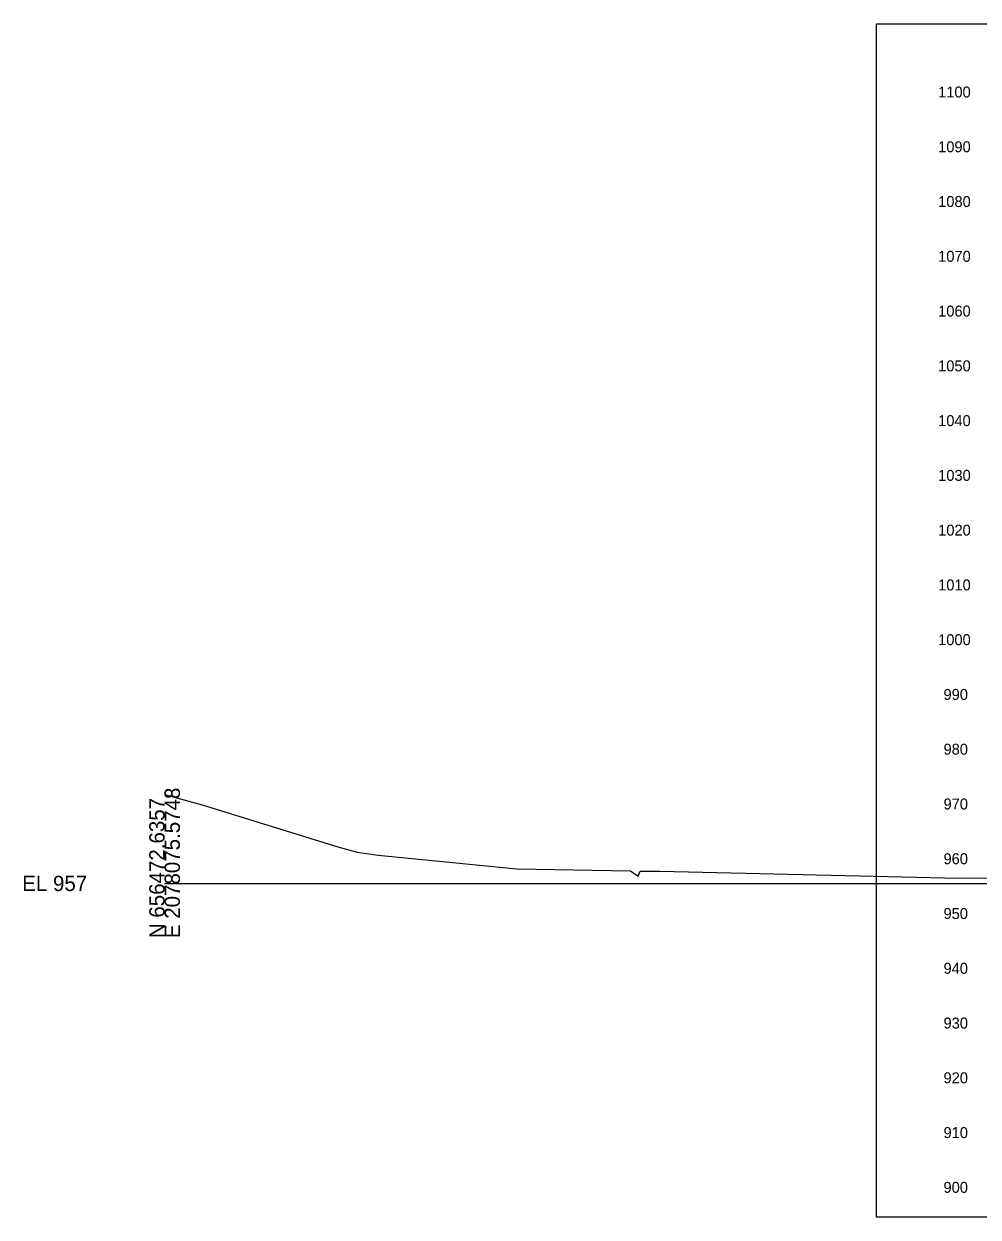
# Model space of a CAD drawing. Extents: x 80 to 2092, y 80 to 1076.
# Drawn here: x 1329.3 to 1503.6, y 857.9 to 1075.8 of the extents above; entities that cross this region are included whole.
import ezdxf

# ---------------------------------------------------------------- set-up
doc = ezdxf.new("R2010")
doc.units = 0
for name, color, linetype in [('DESIGN - SHEET - Corner Text', 7, 'Continuous'), ('DESIGN - SHEET - Light Grid', 7, 'Continuous'), ('DESIGN - SHEET - Plot Shape', 7, 'Continuous'), ('SURVEY - GROUND - Top of Ground', 7, 'Continuous')]:
    doc.layers.add(name, color=color, linetype=linetype)

msp = doc.modelspace()

# ---------------------------------------------------------------- linework, layer by layer
at = {"layer": 'DESIGN - SHEET - Light Grid'}
msp.add_line((1355.01, 918.83), (1655.01, 918.83), dxfattribs=at)
at = {"layer": 'DESIGN - SHEET - Plot Shape'}
msp.add_lwpolyline([(1485.01, 1075.77), (1825.01, 1075.77), (1825.01, 857.89), (1485.01, 857.89)], close=True, dxfattribs=at)
at = {"layer": 'SURVEY - GROUND - Top of Ground'}
msp.add_lwpolyline([(1355.01, 935.08), (1361.89, 933.2), (1386.67, 925.51), (1390.2, 924.54), (1394, 924.01), (1419.31, 921.5), (1440.05, 921.12), (1441.49, 920.17), (1441.85, 921.09), (1444.57, 921.06), (1445.42, 921.06), (1500.1, 919.81), (1538.91, 919.96), (1545.12, 920.01), (1565.75, 919.98), (1603.18, 920.44), (1604.89, 920.4), (1605.02, 920.29), (1605.25, 920.4), (1605.25, 920.4), (1605.25, 920.4)], dxfattribs=at)

# ---------------------------------------------------------------- texts
at = {"layer": 'DESIGN - SHEET - Corner Text'}
for s, p in [('1100', (1496.25, 1062.33)), ('1090', (1496.25, 1052.33)), ('1080', (1496.25, 1042.33)), ('1070', (1496.25, 1032.33)), ('1060', (1496.25, 1022.33)), ('1050', (1496.25, 1012.33)), ('1040', (1496.25, 1002.33)), ('1030', (1496.25, 992.33)), ('1020', (1496.25, 982.33)), ('1010', (1496.25, 972.33)), ('1000', (1496.25, 962.33)), ('990', (1497.23, 952.33)), ('980', (1497.23, 942.33)), ('970', (1497.23, 932.33)), ('960', (1497.23, 922.33)), ('950', (1497.23, 912.33)), ('940', (1497.23, 902.33)), ('930', (1497.23, 892.33)), ('920', (1497.23, 882.33)), ('910', (1497.23, 872.33)), ('900', (1497.23, 862.33))]:
    msp.add_text(s, height=2, dxfattribs=at).set_placement(p)
at = {"layer": 'DESIGN - SHEET - Light Grid'}
for s, p in [('E 2078075.5748', (1357.81, 908.83)), ('N 656472.6357', (1355.01, 908.83))]:
    msp.add_text(s, height=2.8, rotation=90, dxfattribs=at).set_placement(p)
msp.add_text('EL 957', height=2.8, dxfattribs=at).set_placement((1329.01, 917.43))

doc.saveas('drawing.dxf')
